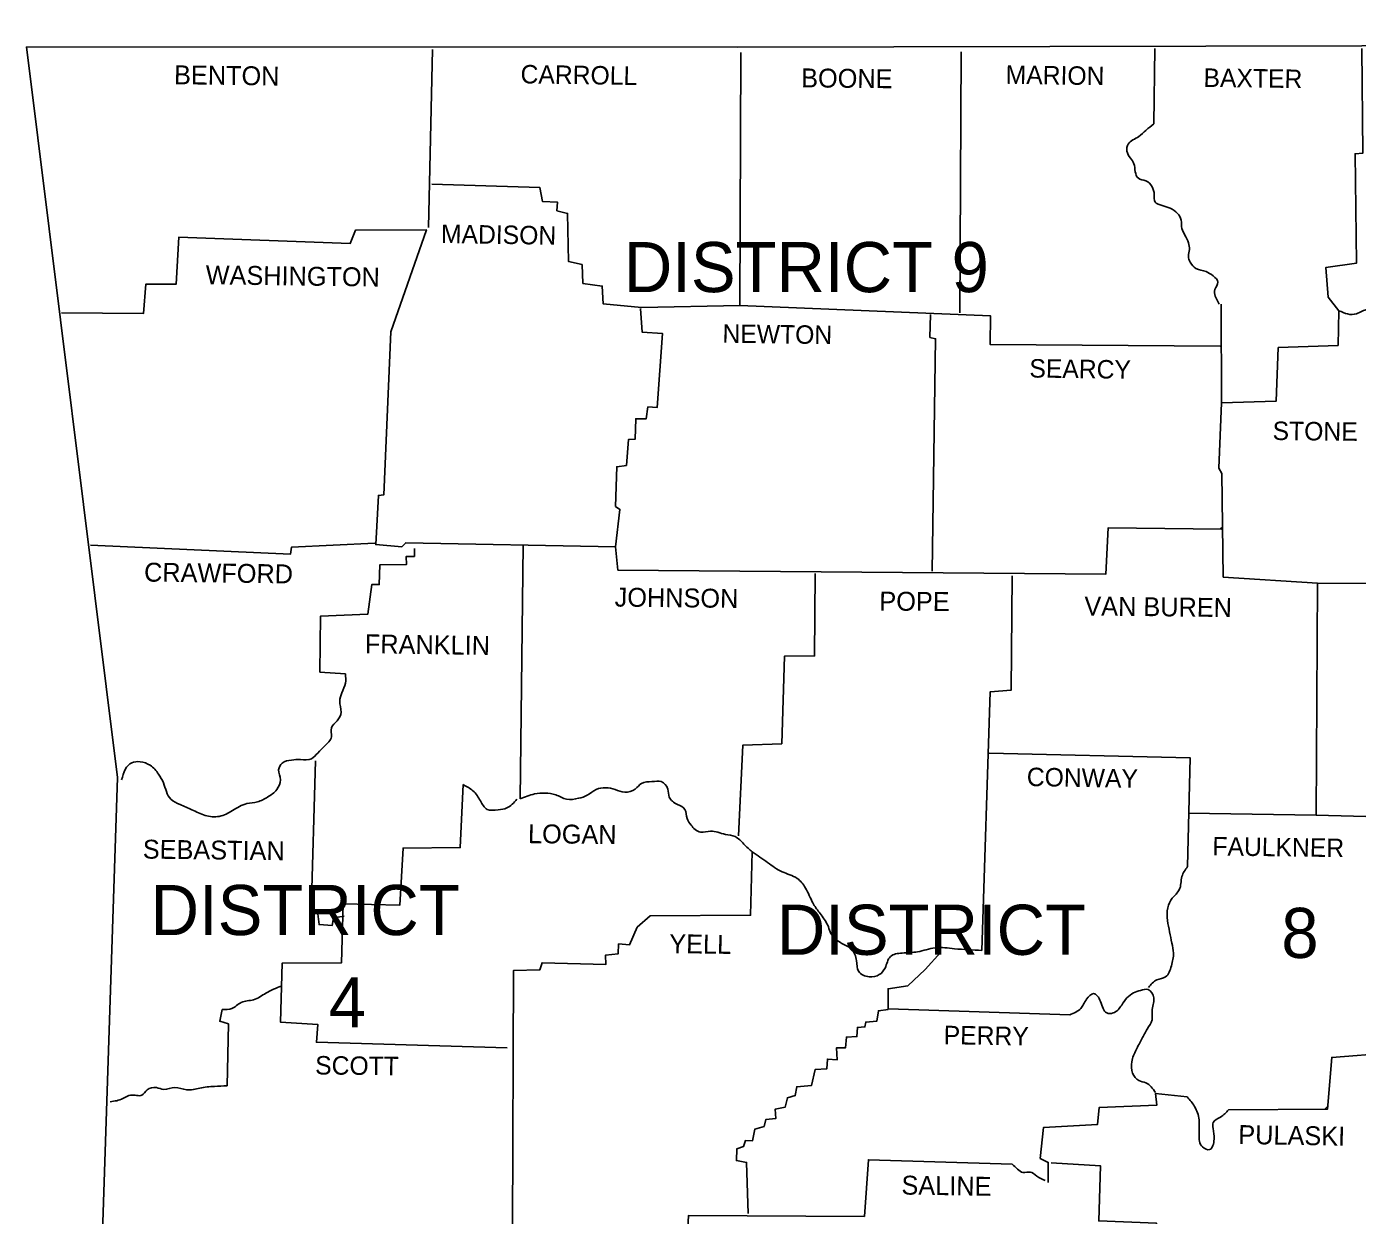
# Model space of a CAD drawing. Extents: x -33639 to 34530, y -17264 to 5867.
# Drawn here: x -17668 to -16002, y -8621 to -7133 of the extents above; entities that cross this region are included whole.
import ezdxf

# ---------------------------------------------------------------- set-up
doc = ezdxf.new("R2010")
doc.units = 0
for name, color, linetype in [('1', 7, 'Continuous'), ('2', 7, 'Continuous'), ('3', 7, 'Continuous')]:
    doc.layers.add(name, color=color, linetype=linetype)

msp = doc.modelspace()

# ---------------------------------------------------------------- linework, layer by layer
at = {"layer": '1'}
for points in [[(-17667.8, -7158.5), (-16777.9, -7159.1), (-15996.9, -7157.4), (-15075.6, -7143.1), (-14648.6, -7133.2)], [(-17667.8, -7158.5), (-17553.9, -8073.2), (-17603.4, -9566.3)], [(-16256.1, -7160.7), (-16257.2, -7254.9)], [(-15996.9, -7160.7), (-15995.8, -7291.7), (-16005.2, -7292.3), (-16003.5, -7429.3), (-16042.1, -7434.8), (-16038.8, -7471.7), (-16025.5, -7488.8), (-16026.6, -7532.2), (-16101.5, -7535), (-16104.2, -7602.1), (-16172.5, -7604.3), (-16175.8, -7685.8), (-16171.9, -7692.4), (-16170.3, -7822.3), (-16052.5, -7830), (-16054.2, -8120), (-15960.6, -8122.8), (-15960.6, -8417.8), (-16034.4, -8423.3), (-16039.9, -8488.2), (-16163.7, -8488.8)], [(-17159.8, -7161.9), (-17164.8, -7384.7)], [(-17160.9, -7330.3), (-17025.5, -7334.7), (-17022.2, -7352.3), (-17003.5, -7352.8), (-17004.1, -7363.8), (-16990.9, -7367.1), (-16989.8, -7427.1), (-16972.7, -7431), (-16971.6, -7454.6), (-16947.4, -7457.9), (-16946.3, -7480), (-16898.4, -7484.9), (-16775.1, -7482.2), (-16774, -7165.7)], [(-16498.3, -7164.6), (-16500, -7491.5)], [(-17624.3, -7491.5), (-17521.4, -7492.1), (-17518.7, -7455.7), (-17480.7, -7455.7), (-17477.4, -7396.9), (-17262.7, -7404.6), (-17256.1, -7388), (-17167.5, -7387.5), (-17212.1, -7515.2), (-17220.9, -7719.4), (-17227.5, -7719.9), (-17230.8, -7781.5), (-17198.4, -7784.3), (-17193.4, -7779.3), (-16930.9, -7784.3), (-16928.1, -7813.5)], [(-16899.5, -7486), (-16897.3, -7515.7), (-16872, -7517.4), (-16878.6, -7609.8), (-16890.2, -7609.3), (-16892.4, -7624.1), (-16905.6, -7624.1), (-16906.1, -7649.5), (-16914.4, -7650), (-16917.1, -7682.5), (-16929.2, -7684.1), (-16930.9, -7733.7), (-16925.4, -7737.5), (-16930.9, -7784.3)], [(-16775.1, -7482.2), (-16461.4, -7495.4), (-16462, -7531.1), (-16174.1, -7533.3)], [(-16536.8, -7493.7), (-16537.4, -7522.3), (-16530.2, -7524), (-16534.6, -7814.6)], [(-16172.5, -7604.3), (-16173, -7480.5)], [(-16928.1, -7813.5), (-16317.2, -7818.4), (-16314.5, -7760.6), (-16172.5, -7762.3)], [(-16174.1, -7761.7), (-16172.5, -7760.1)], [(-17588, -7782.1), (-17337.6, -7793.7), (-17336.5, -7784.9), (-17231.9, -7779.9)], [(-17182.4, -7786.5), (-17182.4, -7796.4), (-17192.8, -7796.4), (-17192.3, -7806.3), (-17225.9, -7806.9), (-17226.4, -7831.6), (-17235.8, -7831.6), (-17240.7, -7868.5), (-17300.2, -7871.3), (-17300.7, -7941.2), (-17268.8, -7943.4)], [(-17046.5, -7782.1), (-17050.3, -8099.7)], [(-16681, -7817.9), (-16681.6, -7920.8), (-16719.5, -7921.3), (-16722.8, -8030.9), (-16771.3, -8032.5), (-16776.8, -8145.9)], [(-16434.5, -7820.6), (-16435.6, -7963.7), (-16462, -7965.9), (-16472.4, -8289.5)], [(-16052.5, -7830), (-15769.6, -7831.6), (-15745.4, -7820.1), (-15747.1, -8035.3), (-15763.6, -8042.4), (-15778.4, -8055.1), (-15783.4, -8060), (-15783.9, -8121.7), (-15963.9, -8121.7)], [(-16463.1, -8042.4), (-16211.6, -8048.5), (-16214.9, -8184.4)], [(-17306.2, -8052.3), (-17311.7, -8241.6), (-17303.5, -8243.8), (-17301.8, -8257.1), (-17285.3, -8258.2), (-17283.7, -8248.8), (-17270.4, -8246.6)], [(-17121.3, -8082), (-17125.2, -8160.7), (-17196.7, -8161.3), (-17200.6, -8232.8), (-17271.5, -8231.2), (-17273.7, -8304.9), (-17348, -8305.5), (-17350.2, -8379.2), (-17303.5, -8382), (-17305.1, -8404.5), (-17066.3, -8411.2)], [(-16214.3, -8117.8), (-16054.2, -8120)], [(-16759.7, -8166.2), (-16761.9, -8245.5), (-16887.4, -8246), (-16903.9, -8260.4), (-16913.3, -8282.4), (-16927, -8281.3), (-16927.6, -8293.9), (-16943.5, -8295.6), (-16943, -8307.1), (-17022.8, -8304.9), (-17025.5, -8313.7), (-17058.6, -8314.8), (-17059.7, -8636.8)], [(-16523.6, -8291.7), (-16543.4, -8313.2), (-16564.9, -8333.6), (-16589.7, -8337.4), (-16589.7, -8363.3), (-16601.8, -8364.9), (-16604, -8378.1), (-16617.7, -8379.2), (-16618.8, -8385.3), (-16628.2, -8385.8), (-16628.7, -8397.4), (-16641.9, -8397.9), (-16643, -8411.2), (-16654.1, -8411.2), (-16653.5, -8426.6), (-16665.6, -8425.5), (-16666.2, -8437.6), (-16681, -8438.7), (-16685.4, -8458.5), (-16704.1, -8460.1), (-16705.8, -8471.1), (-16715.7, -8473.9), (-16718.4, -8485.5), (-16731.1, -8488.2), (-16730, -8499.8), (-16742.7, -8500.9), (-16744.9, -8509.7), (-16756.4, -8513), (-16759.2, -8527.8), (-16768, -8527.3), (-16770.7, -8535), (-16779, -8537.7), (-16779.5, -8552.6), (-16766.9, -8554.8), (-16764.7, -8618.6)], [(-17416.8, -8459), (-17415.2, -8381.4), (-17426.2, -8378.1), (-17422.9, -8363.3)], [(-16362.4, -8369.9), (-16589.1, -8362.7)], [(-16215.4, -8472.8), (-16255, -8468.4), (-16253.4, -8483.2), (-16325.5, -8486), (-16327.7, -8507.5), (-16395.4, -8511.3), (-16399.2, -8549.8), (-16389.3, -8554.8), (-16389.3, -8580.1)], [(-16042.6, -8487.7), (-16039.9, -8484.9)], [(-16434.5, -8557), (-16614.4, -8551.5), (-16619.4, -8622.5), (-16839.5, -8621.4), (-16840.6, -8645.1)], [(-16385.5, -8555.3), (-16323.8, -8559.2), (-16326, -8628), (-16253.9, -8630.7), (-16252.8, -8690.7), (-16218.7, -8693.5), (-16218.7, -8703.9), (-16186.8, -8706.1), (-16185.7, -8744.7), (-16113.1, -8744.7), (-16110.9, -8782.6), (-16043.7, -8785.9), (-16044.3, -8857.5)]]:
    msp.add_lwpolyline(points, dxfattribs=at)
for points in [[(-16257.2, -7254.9), (-16267.2, -7263.1), (-16276, -7270.8), (-16289.2, -7280.2), (-16290.8, -7289), (-16286.4, -7297.8), (-16282, -7304.9), (-16280.4, -7314.8), (-16276.5, -7323.1), (-16267.2, -7326.4), (-16259.4, -7333.6), (-16256.7, -7343.5), (-16255.6, -7352.8), (-16246.8, -7357.2), (-16236.9, -7360.5), (-16227.5, -7367.1), (-16223.1, -7375.4), (-16222, -7385.8), (-16218.2, -7394.1), (-16213.8, -7404), (-16212.7, -7412.3), (-16213.8, -7420.5), (-16211.6, -7428.2), (-16204.4, -7435.9), (-16191.8, -7439.8), (-16182.9, -7445.3), (-16176.9, -7453), (-16180.7, -7462.3), (-16180.2, -7470.6), (-16175.2, -7480.5)], [(-16025.5, -7488.8), (-16003.5, -7492.6), (-15990.3, -7487.7), (-15981, -7502), (-15976, -7513), (-15967.8, -7528.9), (-15954.6, -7533.9), (-15944.6, -7542.7), (-15944.6, -7552.1), (-15953.4, -7560.9), (-15960.1, -7569.7), (-15957.9, -7580.1), (-15955.7, -7594.4), (-15955.7, -7608.2), (-15959, -7620.8), (-15961.7, -7632.4), (-15959, -7642.3), (-15948.5, -7640.7), (-15937.5, -7632.4), (-15925.9, -7632.4), (-15914.9, -7638.5), (-15903.4, -7648.9), (-15891.8, -7646.7), (-15882.5, -7644), (-15869.2, -7640.1), (-15859.9, -7645.1), (-15851.6, -7651.7), (-15841.7, -7662.1), (-15832.4, -7668.7), (-15820.3, -7674.8), (-15805.4, -7678.6), (-15791.6, -7688), (-15789.4, -7703.9), (-15790, -7717.7), (-15791.1, -7734.8), (-15792.2, -7753.5), (-15790.5, -7771.6), (-15784.5, -7783.8), (-15776.8, -7798.1), (-15774.6, -7811.3), (-15775.1, -7832.2)], [(-17268.8, -7943.4), (-17268.8, -7954.9), (-17273.2, -7967), (-17275.9, -7977.5), (-17274.3, -7991.2), (-17279.3, -8002.2), (-17286.4, -8011), (-17286.4, -8022.1), (-17294.7, -8033.6), (-17303.5, -8042.4), (-17311.2, -8049.6), (-17324.9, -8050.7), (-17336.5, -8051.2), (-17348, -8055.1), (-17352.4, -8063.3), (-17350.2, -8076), (-17354.7, -8088.1), (-17366.2, -8097.5), (-17378.9, -8103.5), (-17392.1, -8105.7), (-17410.2, -8114.5), (-17426.7, -8121.7), (-17444.4, -8120.6), (-17460.9, -8113.4), (-17475.7, -8106.8), (-17487.3, -8100.2), (-17496.6, -8079.8), (-17502.7, -8068.8), (-17513.2, -8057.8), (-17525.8, -8053.4), (-17536.3, -8054.5), (-17548.9, -8076)], [(-17050.3, -8099.7), (-17032.1, -8093.6), (-17018.9, -8092.5), (-17005.7, -8094.7), (-16992, -8100.2), (-16977.1, -8099.1), (-16966.1, -8095.3), (-16955.1, -8088.1), (-16943, -8085.9), (-16931.4, -8088.1), (-16919.3, -8091.4), (-16906.1, -8087.5), (-16898.4, -8080.4), (-16885.2, -8078.2), (-16873.6, -8078.2), (-16865.4, -8087.5), (-16863.7, -8097.5), (-16853.3, -8106.8), (-16843.9, -8112.9), (-16841.2, -8124.4), (-16836.2, -8132.7), (-16831.3, -8138.2), (-16824.1, -8141.5), (-16812, -8140.4), (-16793.3, -8144.2), (-16781.2, -8147), (-16770.2, -8156.3), (-16759.7, -8166.2)], [(-17121.3, -8082), (-17109.2, -8089.7), (-17099.8, -8102.4), (-17091.6, -8112.9), (-17077.8, -8113.4), (-17066.8, -8111.2), (-17054.2, -8100.2)], [(-16759.7, -8166.2), (-16740.5, -8179.5), (-16722.3, -8191), (-16703.6, -8199.3), (-16693.1, -8211.4), (-16683.8, -8230.1), (-16676.1, -8241.6), (-16666.2, -8256), (-16659, -8271.9), (-16647.4, -8280.7), (-16635.3, -8288.4), (-16629.3, -8302.2), (-16626.5, -8315.9), (-16613.3, -8322.5), (-16600.7, -8319.8), (-16593.5, -8311.5), (-16586.9, -8297.2), (-16572, -8292.8), (-16552.8, -8291.2), (-16530.8, -8286.2), (-16506.6, -8287.3), (-16472.4, -8289.5)], [(-16214.9, -8184.4), (-16222, -8197.1), (-16225.3, -8213.6), (-16234.1, -8224), (-16239.6, -8236.1), (-16240.2, -8252.1), (-16237.4, -8266.4), (-16234.7, -8280.2), (-16232.5, -8292.8), (-16235.2, -8308.8), (-16242.4, -8322.5), (-16253.4, -8326.4), (-16263.8, -8335.8)], [(-17422.9, -8363.3), (-17410.8, -8362.2), (-17399.2, -8354.5), (-17383.8, -8351.2), (-17368.4, -8342.9), (-17349.1, -8334.1)], [(-16362.4, -8369.9), (-16348.6, -8362.2), (-16341.4, -8350.6), (-16332.6, -8343.5), (-16323.8, -8353.4), (-16316.1, -8367.7), (-16307.9, -8367.7), (-16297.4, -8357.8), (-16290.8, -8349), (-16282.6, -8342.4), (-16273.8, -8339.6), (-16264.4, -8338.5), (-16257.2, -8349), (-16259.4, -8365.5), (-16259.4, -8376.5), (-16265.5, -8388), (-16272.1, -8400.1), (-16279.3, -8413.9), (-16284.8, -8428.8), (-16283.7, -8443.1), (-16276, -8452.4), (-16267.2, -8455.2), (-16255, -8467.3)], [(-17416.8, -8459), (-17432.8, -8459.6), (-17451, -8461.8), (-17467.5, -8464), (-17482.3, -8461.2), (-17496.1, -8463.4), (-17505.4, -8461.2), (-17517, -8464), (-17523.6, -8470.6), (-17537.4, -8470.6), (-17547.3, -8475), (-17563.2, -8478.8)], [(-16215.4, -8472.8), (-16206.1, -8484.9), (-16200.6, -8501.4), (-16200.6, -8520.1), (-16196.2, -8535.5), (-16187.4, -8538.8), (-16181.8, -8525.6), (-16182.9, -8512.4), (-16182.9, -8504.7), (-16173.6, -8498.1), (-16163.7, -8488.8)], [(-16393.2, -8577.4), (-16403.6, -8571.9), (-16411.9, -8566.9), (-16420.7, -8567.5), (-16427.9, -8563.1), (-16434.5, -8557)]]:
    msp.add_spline(points, degree=3, dxfattribs=at)

# ---------------------------------------------------------------- texts
at = {"layer": '2'}
for s, height, rotation, p in [('BENTON', 23.67, 359.2527, (-17483.4, -7205.3)), ('CARROLL', 23.11, 359.1481, (-17049.8, -7204.2)), ('BOONE', 23.67, 359.4001, (-16698.6, -7209.2)), ('MARION', 23.11, 359.1854, (-16442.7, -7204.8)), ('BAXTER', 23.11, 359.2559, (-16195.1, -7208.6)), ('MADISON', 23.11, 359.0906, (-17149.4, -7404)), ('WASHINGTON', 23.66, 359.232, (-17443.8, -7455.7)), ('NEWTON', 23.11, 359.2717, (-16797.1, -7528.9)), ('SEARCY', 23.11, 359.2527, (-16413, -7572.4)), ('STONE', 23.11, 359.4001, (-16108.6, -7650.6)), ('CRAWFORD', 23.66, 359.2771, (-17520.9, -7827.8)), ('JOHNSON', 23.67, 359.3514, (-16932, -7859.1)), ('POPE', 23.67, 359.6155, (-16600.7, -7864.1)), ('VAN BUREN', 23.67, 359.3508, (-16344.2, -7870.2)), ('FRANKLIN', 23.67, 359.1815, (-17244.6, -7917.5)), ('CONWAY', 23.11, 359.0371, (-16416.3, -8083.7)), ('LOGAN', 23.67, 359.3969, (-17040.4, -8155.2)), ('SEBASTIAN', 23.66, 359.2816, (-17522.5, -8174.5)), ('FAULKNER', 23.11, 359.2486, (-16184, -8170.6)), ('YELL', 23.67, 359.1987, (-16863.7, -8292.8)), ('PERRY', 23.11, 359.0858, (-16520.3, -8406.8)), ('SCOTT', 23.11, 359.4063, (-17306.8, -8444.7)), ('PULASKI', 23.67, 359.053, (-16151.6, -8531.7)), ('SALINE', 23.67, 359.1491, (-16573.1, -8595))]:
    msp.add_text(s, height=height, rotation=rotation, dxfattribs=at).set_placement(p)
at = {"layer": '3'}
for s, height, p in [('DISTRICT 9', 62.74, (-16920.4, -7465.6)), ('DISTRICT', 62.74, (-17512.6, -8270.3)), ('DISTRICT', 62.74, (-16728.9, -8295)), ('8', 62.7, (-16097.6, -8298.9)), ('4', 62.7, (-17289.7, -8385.8))]:
    msp.add_text(s, height=height, dxfattribs=at).set_placement(p)

doc.saveas('drawing.dxf')
